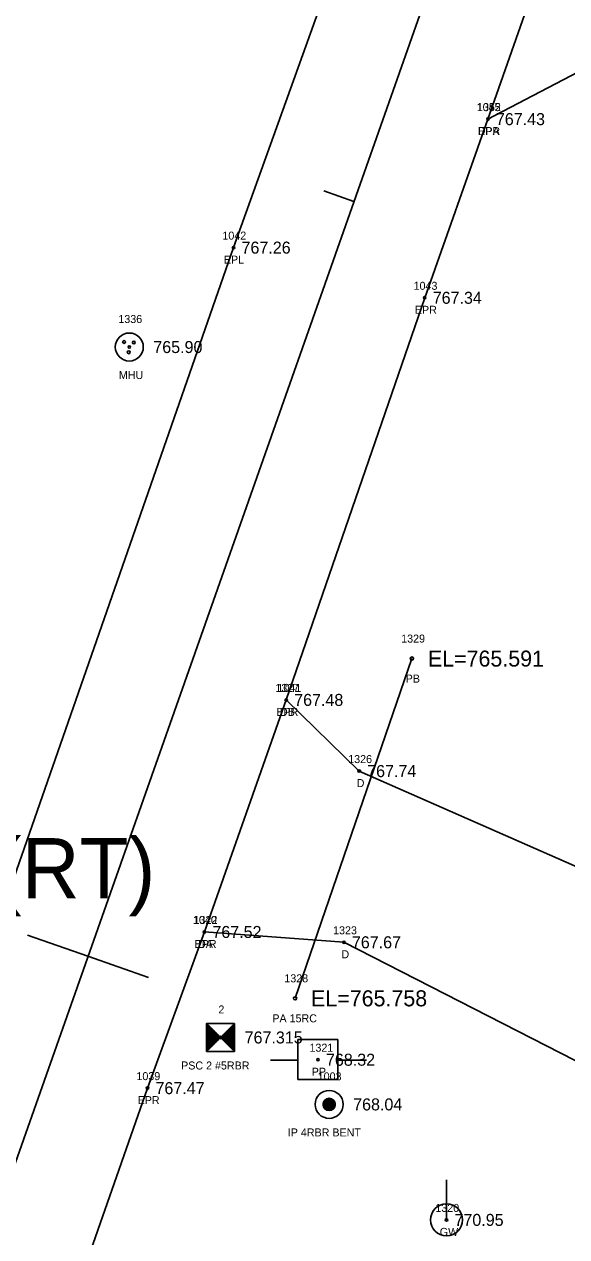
# Model space of a CAD drawing. Extents: x 1736563 to 1738032, y 1150548 to 1154248.
# Drawn here: x 1736933.8 to 1737001.6, y 1151294.7 to 1151446.2 of the extents above; entities that cross this region are included whole.
import ezdxf

# ---------------------------------------------------------------- set-up
doc = ezdxf.new("R2010")
doc.units = 0
for name, color, linetype in [('RD_EX_DR_Inlet', 7, 'Continuous'), ('RD_EX_DR_Pipe', 7, 'Continuous'), ('RD_EX_DR_Pipe_txCode', 7, 'Continuous'), ('RD_EX_Driveway', 7, 'Continuous'), ('RD_EX_Driveway_txCode', 7, 'Continuous'), ('RD_EX_DV_Prop_txCode', 7, 'Continuous'), ('RD_EX_DV_PropPin', 7, 'Continuous'), ('RD_EX_Road', 7, 'Continuous'), ('RD_EX_Road_txCode', 7, 'Continuous'), ('RD_EX_TX_Driveway_ELEV', 7, 'Continuous'), ('RD_EX_TX_DV_Prop_ELEV', 7, 'Continuous'), ('RD_EX_TX_Road_ELEV', 7, 'Continuous'), ('RD_EX_TX_UT_ELEV', 7, 'Continuous'), ('RD_EX_UT', 7, 'Continuous'), ('RD_EX_UT_txCode', 7, 'Continuous'), ('RD_HC_Cl', 7, 'Continuous'), ('RD_HC_Data', 7, 'Continuous'), ('RD_HC_Data_Tic', 7, 'Continuous'), ('RD_HC_Survey', 7, 'Continuous'), ('RD_HC_Survey_ELEV', 7, 'Continuous'), ('RD_HC_txCode', 7, 'Continuous'), ('RD_SMD_Locator', 7, 'Continuous'), ('RD_TX_Pipe_ElevEX', 7, 'Continuous')]:
    doc.layers.add(name, color=color, linetype=linetype)

msp = doc.modelspace()

# ---------------------------------------------------------------- linework, layer by layer
at = {"layer": 'RD_EX_DR_Inlet'}
for centre, radius in [((1736946.9, 1151405.85), 1.75), ((1736946.24, 1151406.48), 0.175), ((1736947.46, 1151406.41), 0.175), ((1736946.82, 1151405.19), 0.175)]:
    msp.add_circle(centre, radius, dxfattribs=at)
at = {"layer": 'RD_EX_DR_Pipe'}
msp.add_line((1736967.61, 1151324.49), (1736982.21, 1151366.93), dxfattribs=at)
at = {"layer": 'RD_EX_Driveway'}
for points in [[(1736991.7, 1151434.32), (1737006.79, 1151442.2), (1737013.05, 1151443.64), (1737078.69, 1151415.68)], [(1737067.31, 1151312.55), (1736975.62, 1151352.88), (1736966.5, 1151361.77)], [(1736956.28, 1151332.78), (1736973.71, 1151331.49), (1737051.36, 1151291.79)]]:
    msp.add_lwpolyline(points, dxfattribs=at)
at = {"layer": 'RD_EX_DV_PropPin'}
for p, q in [((1736971.13, 1151311.05), (1736971.13, 1151311.44)), ((1736971.17, 1151310.94), (1736971.17, 1151311.54)), ((1736971.2, 1151310.87), (1736971.2, 1151311.61)), ((1736971.24, 1151310.82), (1736971.24, 1151311.67)), ((1736971.27, 1151310.77), (1736971.27, 1151311.72)), ((1736971.31, 1151310.73), (1736971.31, 1151311.76)), ((1736971.34, 1151310.69), (1736971.34, 1151311.79)), ((1736971.38, 1151310.66), (1736971.38, 1151311.82)), ((1736971.41, 1151310.63), (1736971.41, 1151311.85)), ((1736971.45, 1151310.61), (1736971.45, 1151311.88)), ((1736971.48, 1151310.59), (1736971.48, 1151311.9)), ((1736971.52, 1151310.57), (1736971.52, 1151311.92)), ((1736971.55, 1151310.55), (1736971.55, 1151311.94)), ((1736971.59, 1151310.54), (1736971.59, 1151311.95)), ((1736971.62, 1151310.52), (1736971.62, 1151311.96)), ((1736971.66, 1151310.51), (1736971.66, 1151311.97)), ((1736971.69, 1151310.5), (1736971.69, 1151311.98)), ((1736971.73, 1151310.49), (1736971.73, 1151311.99)), ((1736971.76, 1151310.49), (1736971.76, 1151312)), ((1736971.8, 1151310.48), (1736971.8, 1151312)), ((1736971.83, 1151310.48), (1736971.83, 1151312)), ((1736971.87, 1151310.48), (1736971.87, 1151312)), ((1736971.9, 1151310.48), (1736971.9, 1151312)), ((1736971.94, 1151310.48), (1736971.94, 1151312)), ((1736971.97, 1151310.49), (1736971.97, 1151312)), ((1736972.01, 1151310.49), (1736972.01, 1151311.99)), ((1736972.04, 1151310.5), (1736972.04, 1151311.98)), ((1736972.08, 1151310.51), (1736972.08, 1151311.97)), ((1736972.11, 1151310.52), (1736972.11, 1151311.96)), ((1736972.15, 1151310.54), (1736972.15, 1151311.95)), ((1736972.18, 1151310.55), (1736972.18, 1151311.94)), ((1736972.22, 1151310.57), (1736972.22, 1151311.92)), ((1736972.25, 1151310.59), (1736972.25, 1151311.9)), ((1736972.29, 1151310.61), (1736972.29, 1151311.88)), ((1736972.32, 1151310.63), (1736972.32, 1151311.85)), ((1736972.36, 1151310.66), (1736972.36, 1151311.82)), ((1736972.39, 1151310.69), (1736972.39, 1151311.79)), ((1736972.43, 1151310.73), (1736972.43, 1151311.76)), ((1736972.46, 1151310.77), (1736972.46, 1151311.72)), ((1736972.5, 1151310.82), (1736972.5, 1151311.67)), ((1736972.53, 1151310.87), (1736972.53, 1151311.61)), ((1736972.57, 1151310.94), (1736972.57, 1151311.54)), ((1736972.6, 1151311.05), (1736972.6, 1151311.44))]:
    msp.add_line(p, q, dxfattribs=at)
for radius in [1.75, 0.761]:
    msp.add_circle((1736971.87, 1151311.24), radius, dxfattribs=at)
at = {"layer": 'RD_EX_Road'}
for points in [[(1736868.01, 1151157.6), (1736882.54, 1151196.52), (1736892.4, 1151226.58), (1736911.77, 1151279.81), (1736926.32, 1151321.94), (1736959.92, 1151418.27), (1736977.6, 1151467.57), (1736993.86, 1151514.24), (1737026.63, 1151607.21), (1737059.17, 1151698.64), (1737091.53, 1151790.84), (1737119.9, 1151870.3), (1737125.51, 1151887.21), (1737129.74, 1151897.31), (1737157.61, 1151979.19), (1737191.07, 1152073.18), (1737224.57, 1152167.62), (1737258.08, 1152262.33), (1737292.51, 1152359.5), (1737326.83, 1152457.35), (1737361.84, 1152556.63), (1737380.81, 1152611.37), (1737392.07, 1152607.38)], [(1736891.67, 1151150.12), (1736912.85, 1151210.27), (1736923.53, 1151240.29), (1736927.25, 1151250.75), (1736949.17, 1151313.27), (1736956.28, 1151332.78), (1736966.5, 1151361.77), (1736983.81, 1151412), (1736991.7, 1151434.32), (1737008.48, 1151482.13), (1737017.08, 1151506.24), (1737050.57, 1151600.07), (1737082.25, 1151690.44), (1737114.69, 1151782.27), (1737149.29, 1151879.88)]]:
    msp.add_lwpolyline(points, dxfattribs=at)
at = {"layer": 'RD_EX_UT'}
for p, q in [((1736972.96, 1151319.33), (1736967.96, 1151319.33)), ((1736967.96, 1151319.33), (1736967.96, 1151314.33)), ((1736972.96, 1151314.33), (1736972.96, 1151319.33)), ((1736964.53, 1151316.76), (1736968, 1151316.76)), ((1736972.89, 1151316.76), (1736976.53, 1151316.76)), ((1736967.96, 1151314.33), (1736972.96, 1151314.33)), ((1736986.53, 1151296.81), (1736986.53, 1151301.81))]:
    msp.add_line(p, q, dxfattribs=at)
msp.add_circle((1736986.53, 1151296.81), 2, dxfattribs=at)
at = {"layer": 'RD_HC_Cl'}
msp.add_line((1736879.96, 1151154.46), (1737935.1, 1154148.31), dxfattribs=at)
at = {"layer": 'RD_HC_Data_Tic'}
for p, q in [((1736974.97, 1151424.05), (1736971.2, 1151425.38)), ((1736941.73, 1151329.74), (1736934.19, 1151332.4)), ((1736941.73, 1151329.74), (1736949.28, 1151327.08))]:
    msp.add_line(p, q, dxfattribs=at)
at = {"layer": 'RD_HC_Survey'}
for p, q in [((1736956.56, 1151321.35), (1736960.06, 1151317.85)), ((1736960.06, 1151321.35), (1736956.56, 1151317.85)), ((1736956.58, 1151321.32), (1736956.58, 1151317.87)), ((1736956.61, 1151321.3), (1736956.61, 1151317.9)), ((1736956.63, 1151321.28), (1736956.63, 1151317.92)), ((1736956.66, 1151321.25), (1736956.66, 1151317.95)), ((1736956.68, 1151321.23), (1736956.68, 1151317.97)), ((1736956.71, 1151321.2), (1736956.71, 1151318)), ((1736956.73, 1151321.18), (1736956.73, 1151318.02)), ((1736956.76, 1151321.15), (1736956.76, 1151318.05)), ((1736956.78, 1151321.13), (1736956.78, 1151318.07)), ((1736956.81, 1151321.1), (1736956.81, 1151318.1)), ((1736956.83, 1151321.08), (1736956.83, 1151318.12)), ((1736956.86, 1151321.05), (1736956.86, 1151318.15)), ((1736956.88, 1151321.03), (1736956.88, 1151318.17)), ((1736956.91, 1151321), (1736956.91, 1151318.2)), ((1736956.93, 1151320.98), (1736956.93, 1151318.22)), ((1736956.96, 1151320.95), (1736956.96, 1151318.25)), ((1736956.98, 1151320.93), (1736956.98, 1151318.27)), ((1736957, 1151320.9), (1736957, 1151318.29)), ((1736957.03, 1151320.88), (1736957.03, 1151318.32)), ((1736957.05, 1151320.85), (1736957.05, 1151318.34)), ((1736957.08, 1151320.83), (1736957.08, 1151318.37)), ((1736957.1, 1151320.8), (1736957.1, 1151318.39)), ((1736957.13, 1151320.78), (1736957.13, 1151318.42)), ((1736957.15, 1151320.76), (1736957.15, 1151318.44)), ((1736957.18, 1151320.73), (1736957.18, 1151318.47)), ((1736957.2, 1151320.71), (1736957.2, 1151318.49)), ((1736957.23, 1151320.68), (1736957.23, 1151318.52)), ((1736957.25, 1151320.66), (1736957.25, 1151318.54)), ((1736957.28, 1151320.63), (1736957.28, 1151318.57)), ((1736957.3, 1151320.61), (1736957.3, 1151318.59)), ((1736957.33, 1151320.58), (1736957.33, 1151318.62)), ((1736957.35, 1151320.56), (1736957.35, 1151318.64)), ((1736957.38, 1151320.53), (1736957.38, 1151318.67)), ((1736957.4, 1151320.51), (1736957.4, 1151318.69)), ((1736957.43, 1151320.48), (1736957.43, 1151318.72)), ((1736957.45, 1151320.46), (1736957.45, 1151318.74)), ((1736957.47, 1151320.43), (1736957.47, 1151318.77)), ((1736957.5, 1151320.41), (1736957.5, 1151318.79)), ((1736957.52, 1151320.38), (1736957.52, 1151318.81)), ((1736957.55, 1151320.36), (1736957.55, 1151318.84)), ((1736957.57, 1151320.33), (1736957.57, 1151318.86)), ((1736957.6, 1151320.31), (1736957.6, 1151318.89)), ((1736957.62, 1151320.29), (1736957.62, 1151318.91)), ((1736957.65, 1151320.26), (1736957.65, 1151318.94)), ((1736957.67, 1151320.24), (1736957.67, 1151318.96)), ((1736957.7, 1151320.21), (1736957.7, 1151318.99)), ((1736957.72, 1151320.19), (1736957.72, 1151319.01)), ((1736957.75, 1151320.16), (1736957.75, 1151319.04)), ((1736957.77, 1151320.14), (1736957.77, 1151319.06)), ((1736957.8, 1151320.11), (1736957.8, 1151319.09)), ((1736957.82, 1151320.09), (1736957.82, 1151319.11)), ((1736958.8, 1151320.09), (1736958.8, 1151319.11)), ((1736958.82, 1151320.11), (1736958.82, 1151319.09)), ((1736958.85, 1151320.14), (1736958.85, 1151319.06)), ((1736958.87, 1151320.16), (1736958.87, 1151319.04)), ((1736958.9, 1151320.19), (1736958.9, 1151319.01)), ((1736958.92, 1151320.21), (1736958.92, 1151318.99)), ((1736958.95, 1151320.24), (1736958.95, 1151318.96)), ((1736958.97, 1151320.26), (1736958.97, 1151318.94)), ((1736959, 1151320.29), (1736959, 1151318.91)), ((1736959.02, 1151320.31), (1736959.02, 1151318.89)), ((1736959.04, 1151320.33), (1736959.04, 1151318.86)), ((1736959.07, 1151320.36), (1736959.07, 1151318.84)), ((1736959.09, 1151320.38), (1736959.09, 1151318.81)), ((1736959.12, 1151320.41), (1736959.12, 1151318.79)), ((1736959.14, 1151320.43), (1736959.14, 1151318.77)), ((1736959.17, 1151320.46), (1736959.17, 1151318.74)), ((1736959.19, 1151320.48), (1736959.19, 1151318.72)), ((1736959.22, 1151320.51), (1736959.22, 1151318.69)), ((1736959.24, 1151320.53), (1736959.24, 1151318.67)), ((1736959.27, 1151320.56), (1736959.27, 1151318.64)), ((1736959.29, 1151320.58), (1736959.29, 1151318.62)), ((1736959.32, 1151320.61), (1736959.32, 1151318.59)), ((1736959.34, 1151320.63), (1736959.34, 1151318.57)), ((1736959.37, 1151320.66), (1736959.37, 1151318.54)), ((1736959.39, 1151320.68), (1736959.39, 1151318.52)), ((1736959.42, 1151320.71), (1736959.42, 1151318.49)), ((1736959.44, 1151320.73), (1736959.44, 1151318.47)), ((1736959.47, 1151320.76), (1736959.47, 1151318.44)), ((1736959.49, 1151320.78), (1736959.49, 1151318.42)), ((1736959.51, 1151320.8), (1736959.51, 1151318.39)), ((1736959.54, 1151320.83), (1736959.54, 1151318.37)), ((1736959.56, 1151320.85), (1736959.56, 1151318.34)), ((1736959.59, 1151320.88), (1736959.59, 1151318.32)), ((1736959.61, 1151320.9), (1736959.61, 1151318.29)), ((1736959.64, 1151320.93), (1736959.64, 1151318.27)), ((1736959.66, 1151320.95), (1736959.66, 1151318.25)), ((1736959.69, 1151320.98), (1736959.69, 1151318.22)), ((1736959.71, 1151321), (1736959.71, 1151318.2)), ((1736959.74, 1151321.03), (1736959.74, 1151318.17)), ((1736959.76, 1151321.05), (1736959.76, 1151318.15)), ((1736959.79, 1151321.08), (1736959.79, 1151318.12)), ((1736959.81, 1151321.1), (1736959.81, 1151318.1)), ((1736959.84, 1151321.13), (1736959.84, 1151318.07)), ((1736959.86, 1151321.15), (1736959.86, 1151318.05)), ((1736959.89, 1151321.18), (1736959.89, 1151318.02)), ((1736959.91, 1151321.2), (1736959.91, 1151318)), ((1736959.94, 1151321.23), (1736959.94, 1151317.97)), ((1736959.96, 1151321.25), (1736959.96, 1151317.95)), ((1736959.98, 1151321.28), (1736959.98, 1151317.92)), ((1736960.01, 1151321.3), (1736960.01, 1151317.9)), ((1736960.03, 1151321.32), (1736960.03, 1151317.87)), ((1736957.85, 1151320.06), (1736957.85, 1151319.14)), ((1736957.87, 1151320.04), (1736957.87, 1151319.16)), ((1736957.9, 1151320.01), (1736957.9, 1151319.19)), ((1736957.92, 1151319.99), (1736957.92, 1151319.21)), ((1736957.95, 1151319.96), (1736957.95, 1151319.24)), ((1736957.97, 1151319.94), (1736957.97, 1151319.26)), ((1736957.99, 1151319.91), (1736957.99, 1151319.28)), ((1736958.02, 1151319.89), (1736958.02, 1151319.31)), ((1736958.04, 1151319.86), (1736958.04, 1151319.33)), ((1736958.07, 1151319.84), (1736958.07, 1151319.36)), ((1736958.09, 1151319.81), (1736958.09, 1151319.38)), ((1736958.12, 1151319.79), (1736958.12, 1151319.41)), ((1736958.14, 1151319.77), (1736958.14, 1151319.43)), ((1736958.17, 1151319.74), (1736958.17, 1151319.46)), ((1736958.19, 1151319.72), (1736958.19, 1151319.48)), ((1736958.22, 1151319.69), (1736958.22, 1151319.51)), ((1736958.24, 1151319.67), (1736958.24, 1151319.53)), ((1736958.27, 1151319.64), (1736958.27, 1151319.56)), ((1736958.29, 1151319.62), (1736958.29, 1151319.58)), ((1736958.33, 1151319.62), (1736958.33, 1151319.58)), ((1736958.35, 1151319.64), (1736958.35, 1151319.56)), ((1736958.38, 1151319.67), (1736958.38, 1151319.53)), ((1736958.4, 1151319.69), (1736958.4, 1151319.51)), ((1736958.43, 1151319.72), (1736958.43, 1151319.48)), ((1736958.45, 1151319.74), (1736958.45, 1151319.46)), ((1736958.48, 1151319.77), (1736958.48, 1151319.43)), ((1736958.5, 1151319.79), (1736958.5, 1151319.41)), ((1736958.52, 1151319.81), (1736958.52, 1151319.38)), ((1736958.55, 1151319.84), (1736958.55, 1151319.36)), ((1736958.57, 1151319.86), (1736958.57, 1151319.33)), ((1736958.6, 1151319.89), (1736958.6, 1151319.31)), ((1736958.62, 1151319.91), (1736958.62, 1151319.28)), ((1736958.65, 1151319.94), (1736958.65, 1151319.26)), ((1736958.67, 1151319.96), (1736958.67, 1151319.24)), ((1736958.7, 1151319.99), (1736958.7, 1151319.21)), ((1736958.72, 1151320.01), (1736958.72, 1151319.19)), ((1736958.75, 1151320.04), (1736958.75, 1151319.16)), ((1736958.77, 1151320.06), (1736958.77, 1151319.14))]:
    msp.add_line(p, q, dxfattribs=at)
msp.add_lwpolyline([(1736960.06, 1151321.35), (1736956.56, 1151321.35), (1736956.56, 1151317.85), (1736960.06, 1151317.85)], close=True, dxfattribs=at)
at = {"layer": 'RD_SMD_Locator'}
for centre, radius in [((1736991.7, 1151434.32), 0.15), ((1736991.7, 1151434.32), 0.15), ((1736959.92, 1151418.27), 0.15), ((1736983.81, 1151412), 0.15), ((1736946.9, 1151405.85), 0.15), ((1736982.21, 1151366.93), 0.2), ((1736966.5, 1151361.77), 0.15), ((1736966.5, 1151361.77), 0.15), ((1736975.62, 1151352.88), 0.15), ((1736956.28, 1151332.78), 0.15), ((1736956.28, 1151332.78), 0.15), ((1736973.71, 1151331.49), 0.15), ((1736967.61, 1151324.49), 0.2), ((1736958.31, 1151319.6), 0.15), ((1736970.47, 1151316.82), 0.15), ((1736949.17, 1151313.27), 0.15), ((1736971.87, 1151311.24), 0.15), ((1736986.53, 1151296.81), 0.15)]:
    msp.add_circle(centre, radius, dxfattribs=at)

# ---------------------------------------------------------------- texts
at = {"layer": 'RD_EX_DR_Pipe_txCode'}
for s, p in [('1329', (1736980.87, 1151368.93)), ('PB', (1736981.43, 1151363.93)), ('1328', (1736966.27, 1151326.49)), ('PA 15RC', (1736964.77, 1151321.49))]:
    msp.add_text(s, height=1, dxfattribs=at).set_placement(p)
at = {"layer": 'RD_EX_Driveway_txCode'}
for s, p in [('1352', (1736990.35, 1151435.32)), ('DPA', (1736990.43, 1151432.32)), ('1327', (1736965.15, 1151362.77)), ('DB', (1736965.72, 1151359.77)), ('1326', (1736974.25, 1151353.88)), ('D', (1736975.31, 1151350.88)), ('1322', (1736954.93, 1151333.78)), ('1323', (1736972.36, 1151332.49)), ('DA', (1736955.48, 1151330.78)), ('D', (1736973.4, 1151329.49))]:
    msp.add_text(s, height=1, dxfattribs=at).set_placement(p)
at = {"layer": 'RD_EX_DV_Prop_txCode'}
for s, p in [('1003', (1736970.44, 1151314.24)), ('IP 4RBR BENT', (1736966.7, 1151307.24))]:
    msp.add_text(s, height=1, dxfattribs=at).set_placement(p)
at = {"layer": 'RD_EX_Road_txCode'}
for s, p in [('1045', (1736990.31, 1151435.32)), ('EPR', (1736990.47, 1151432.32)), ('1042', (1736958.53, 1151419.27)), ('EPL', (1736958.71, 1151416.27)), ('1043', (1736982.42, 1151413)), ('EPR', (1736982.58, 1151410)), ('1041', (1736965.4, 1151362.77)), ('EPR', (1736965.27, 1151359.77)), ('1040', (1736954.85, 1151333.78)), ('EPR', (1736955.05, 1151330.78)), ('1039', (1736947.79, 1151314.27)), ('EPR', (1736947.94, 1151311.27))]:
    msp.add_text(s, height=1, dxfattribs=at).set_placement(p)
at = {"layer": 'RD_EX_TX_Driveway_ELEV'}
for s, p in [('767.43', (1736992.7, 1151433.57)), ('767.48', (1736967.5, 1151361.02)), ('767.74', (1736976.62, 1151352.13)), ('767.52', (1736957.28, 1151332.03)), ('767.67', (1736974.71, 1151330.74))]:
    msp.add_text(s, height=1.5, dxfattribs=at).set_placement(p)
at = {"layer": 'RD_EX_TX_DV_Prop_ELEV'}
msp.add_text('768.04', height=1.5, dxfattribs=at).set_placement((1736974.87, 1151310.49))
at = {"layer": 'RD_EX_TX_Road_ELEV'}
for s, p in [('767.43', (1736992.7, 1151433.57)), ('767.26', (1736960.92, 1151417.52)), ('767.34', (1736984.81, 1151411.25)), ('767.48', (1736967.5, 1151361.02)), ('767.52', (1736957.28, 1151332.03)), ('767.47', (1736950.17, 1151312.52))]:
    msp.add_text(s, height=1.5, dxfattribs=at).set_placement(p)
at = {"layer": 'RD_EX_TX_UT_ELEV'}
for s, p in [('765.90', (1736949.9, 1151405.1)), ('770.95', (1736987.53, 1151296.06))]:
    msp.add_text(s, height=1.5, dxfattribs=at).set_placement(p)
at = {"layer": 'RD_EX_UT_txCode'}
for s, p in [('1336', (1736945.53, 1151408.85)), ('MHU', (1736945.6, 1151401.85)), ('1321', (1736969.41, 1151317.82)), ('PP', (1736969.69, 1151314.82)), ('1320', (1736985.14, 1151297.81)), ('GW', (1736985.69, 1151294.81))]:
    msp.add_text(s, height=1, dxfattribs=at).set_placement(p)
at = {"layer": 'RD_HC_Data'}
msp.add_text('    = 35%%d 20\' 53" (RT)', height=7.5, dxfattribs=at).set_placement((1736859, 1151337))
at = {"layer": 'RD_HC_Survey_ELEV'}
for s, p in [('767.315', (1736961.31, 1151318.85)), ('768.32', (1736971.47, 1151316.07))]:
    msp.add_text(s, height=1.5, dxfattribs=at).set_placement(p)
at = {"layer": 'RD_HC_txCode'}
for s, p in [('2', (1736958.03, 1151322.6)), ('PSC 2 #5RBR', (1736953.37, 1151315.6))]:
    msp.add_text(s, height=1, dxfattribs=at).set_placement(p)
at = {"layer": 'RD_TX_Pipe_ElevEX'}
for s, p in [('EL=765.591', (1736984.21, 1151365.93)), ('EL=765.758', (1736969.61, 1151323.49))]:
    msp.add_text(s, height=2, dxfattribs=at).set_placement(p)

doc.saveas('drawing.dxf')
